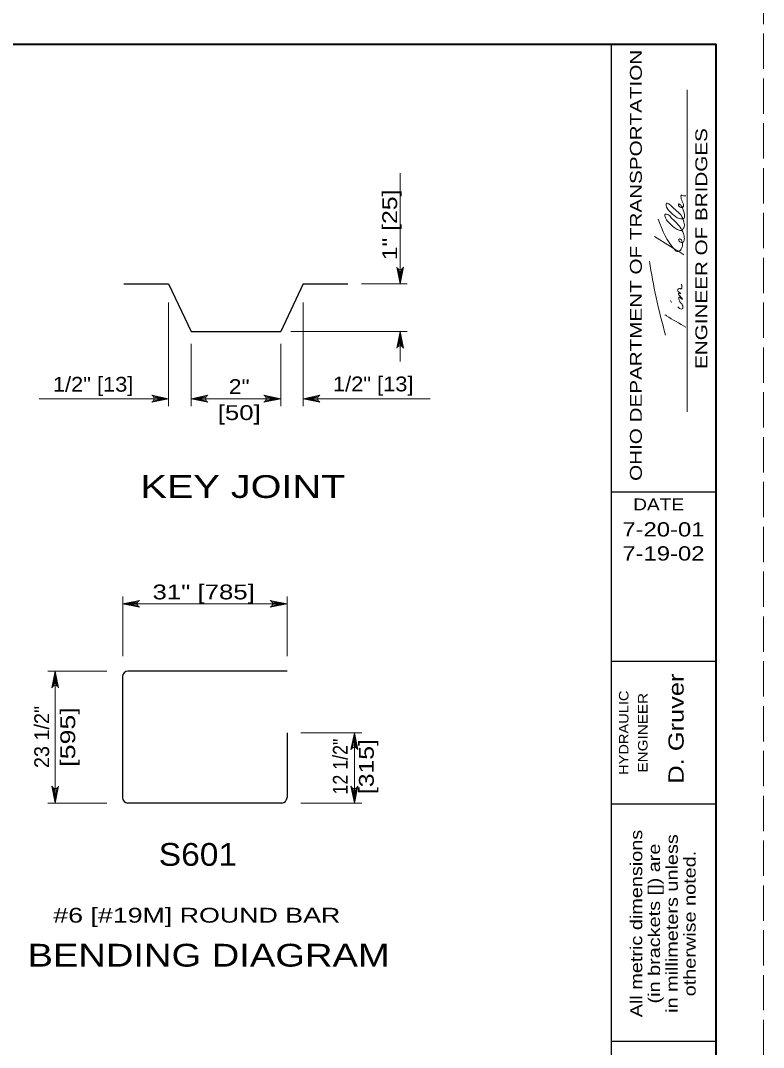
# Model space of a CAD drawing. Extents: x 339.1 to 373.1, y 1412.7 to 1456.7.
# Drawn here: x 365.24 to 373.06, y 1423.68 to 1434.5 of the extents above; entities that cross this region are included whole.
import ezdxf
from ezdxf.enums import TextEntityAlignment as Align

# ---------------------------------------------------------------- set-up
doc = ezdxf.new("R2010")
doc.units = 0
doc.header["$LTSCALE"] = 0.062
doc.linetypes.add('LONG_DASHED', pattern=[7.5, 6, -1.5])
doc.layers.add('1', color=7, linetype='Continuous', lineweight=13)

msp = doc.modelspace()

# ---------------------------------------------------------------- linework, layer by layer
at = {"layer": '1', "lineweight": 25}
for p, q in [((341.0605, 1434.2455), (372.5605, 1434.2455)), ((371.4605, 1413.2455), (371.4605, 1434.2455)), ((372.5605, 1434.2455), (372.5605, 1413.2455)), ((366.32783, 1431.7215), (366.79983, 1431.7215)), ((366.79983, 1431.7215), (367.03583, 1431.22175)), ((368.21583, 1431.7215), (367.97983, 1431.22175)), ((368.21583, 1431.7215), (368.68783, 1431.7215)), ((367.03583, 1431.22175), (367.97983, 1431.22175)), ((372.5605, 1429.52967), (371.4605, 1429.52967)), ((372.5605, 1427.7455), (371.4605, 1427.7455)), ((368.04658, 1427.64575), (366.371, 1427.64575)), ((366.31517, 1427.58658), (366.31517, 1426.31525)), ((368.04658, 1426.99525), (368.04658, 1426.31525)), ((367.99075, 1426.25608), (366.371, 1426.25608)), ((372.5605, 1426.2455), (371.4605, 1426.2455)), ((372.5605, 1423.7455), (371.4605, 1423.7455))]:
    msp.add_line(p, q, dxfattribs=at)
at = {"layer": '1'}
for p, q in [((372.25925, 1430.3765), (372.25925, 1433.76658)), ((369.23558, 1431.7215), (369.23558, 1432.89008)), ((369.21317, 1431.88175), (369.23558, 1431.7215)), ((369.22425, 1431.87625), (369.23558, 1431.7215)), ((369.26033, 1431.88358), (369.23558, 1431.7215)), ((369.25, 1431.8775), (369.23558, 1431.7215)), ((369.23558, 1431.87467), (369.23558, 1431.7215)), ((368.82925, 1431.72217), (369.31142, 1431.72217)), ((372.09175, 1431.52742), (372.08158, 1431.54667)), ((366.79983, 1431.52517), (366.79983, 1430.43508)), ((368.21583, 1431.52517), (368.21583, 1430.43508)), ((368.08683, 1431.22175), (369.31142, 1431.22175)), ((369.21083, 1431.05967), (369.23558, 1431.22175)), ((369.22117, 1431.06575), (369.23558, 1431.22175)), ((369.23558, 1430.90458), (369.23558, 1431.22175)), ((369.23558, 1431.06858), (369.23558, 1431.22175)), ((369.24692, 1431.06692), (369.23558, 1431.22175)), ((369.258, 1431.0615), (369.23558, 1431.22175)), ((367.03583, 1431.09075), (367.03583, 1430.43508)), ((367.97983, 1431.09075), (367.97983, 1430.43508)), ((365.43842, 1430.51375), (366.79983, 1430.51375)), ((366.63775, 1430.489), (366.79983, 1430.51375)), ((366.63958, 1430.53617), (366.79983, 1430.51375)), ((366.64383, 1430.49933), (366.79983, 1430.51375)), ((366.64508, 1430.52508), (366.79983, 1430.51375)), ((366.64667, 1430.51375), (366.79983, 1430.51375)), ((367.19608, 1430.53617), (367.03583, 1430.51375)), ((367.19067, 1430.52508), (367.03583, 1430.51375)), ((367.03583, 1430.51375), (367.72292, 1430.51375)), ((367.189, 1430.51375), (367.03583, 1430.51375)), ((367.19183, 1430.49933), (367.03583, 1430.51375)), ((367.198, 1430.489), (367.03583, 1430.51375)), ((367.69217, 1430.51375), (367.97983, 1430.51375)), ((367.81775, 1430.489), (367.97983, 1430.51375)), ((367.81958, 1430.53617), (367.97983, 1430.51375)), ((367.82383, 1430.49933), (367.97983, 1430.51375)), ((367.82508, 1430.52508), (367.97983, 1430.51375)), ((367.82667, 1430.51375), (367.97983, 1430.51375)), ((368.37608, 1430.53617), (368.21583, 1430.51375)), ((368.37067, 1430.52508), (368.21583, 1430.51375)), ((368.21583, 1430.51375), (369.55125, 1430.51375)), ((368.369, 1430.51375), (368.21583, 1430.51375)), ((368.37183, 1430.49933), (368.21583, 1430.51375)), ((368.378, 1430.489), (368.21583, 1430.51375)), ((366.3195, 1427.80167), (366.3195, 1428.43242)), ((368.04733, 1427.80167), (368.04733, 1428.43242)), ((366.47542, 1428.37617), (366.31517, 1428.35375)), ((366.47, 1428.36508), (366.31517, 1428.35375)), ((366.50417, 1428.35375), (366.31517, 1428.35375)), ((366.46833, 1428.35375), (366.31517, 1428.35375)), ((366.47117, 1428.33933), (366.31517, 1428.35375)), ((366.47733, 1428.32892), (366.31517, 1428.35375)), ((367.36392, 1428.35375), (366.48283, 1428.35375)), ((368.04658, 1428.35375), (367.34017, 1428.35375)), ((367.8845, 1428.32892), (368.04658, 1428.35375)), ((367.88633, 1428.37617), (368.04658, 1428.35375)), ((367.89058, 1428.33933), (368.04658, 1428.35375)), ((367.89183, 1428.36508), (368.04658, 1428.35375)), ((367.89342, 1428.35375), (368.04658, 1428.35375)), ((366.14875, 1427.64575), (365.5285, 1427.64575)), ((365.58242, 1427.48358), (365.60717, 1427.64575)), ((365.59275, 1427.48975), (365.60717, 1427.64575)), ((365.60717, 1427.64575), (365.60717, 1426.732)), ((365.60717, 1427.49258), (365.60717, 1427.64575)), ((365.6185, 1427.49092), (365.60717, 1427.64575)), ((365.62958, 1427.4855), (365.60717, 1427.64575)), ((368.19167, 1426.99683), (368.83325, 1426.99683)), ((368.72983, 1426.83308), (368.75458, 1426.99525)), ((368.74025, 1426.83925), (368.75458, 1426.99525)), ((368.75458, 1426.84208), (368.75458, 1426.99525)), ((368.76592, 1426.84042), (368.75458, 1426.99525)), ((368.777, 1426.835), (368.75458, 1426.99525)), ((368.75458, 1426.99525), (368.75458, 1426.31525)), ((365.60717, 1426.76592), (365.60717, 1426.25617)), ((368.75458, 1426.46167), (368.75458, 1426.25608)), ((365.58475, 1426.41633), (365.60717, 1426.25617)), ((365.59583, 1426.41092), (365.60717, 1426.25617)), ((365.63192, 1426.41825), (365.60717, 1426.25617)), ((365.62158, 1426.41217), (365.60717, 1426.25617)), ((365.60717, 1426.40933), (365.60717, 1426.25617)), ((368.73217, 1426.41633), (368.75458, 1426.25608)), ((368.74325, 1426.41092), (368.75458, 1426.25608)), ((368.77942, 1426.41825), (368.75458, 1426.25608)), ((368.769, 1426.41208), (368.75458, 1426.25608)), ((368.75458, 1426.40925), (368.75458, 1426.25608)), ((366.14875, 1426.25517), (365.5285, 1426.25517)), ((368.19167, 1426.25517), (368.83325, 1426.25517))]:
    msp.add_line(p, q, dxfattribs=at)
at = {"layer": '1', "linetype": 'LONG_DASHED'}
msp.add_lwpolyline([(339.0605, 1412.7455), (373.0605, 1412.7455), (373.0605, 1434.7455), (339.0605, 1434.7455)], close=True, dxfattribs=at)
at = {"layer": '1', "lineweight": 40}
msp.add_lwpolyline([(341.0605, 1434.2455), (372.5605, 1434.2455), (372.5605, 1413.2455), (341.0605, 1413.2455)], close=True, dxfattribs=at)
at = {"layer": '1'}
for points in [[(369.271, 1431.8985), (369.23558, 1431.7215), (369.20017, 1431.8985)], [(369.20017, 1431.04475), (369.23558, 1431.22175), (369.271, 1431.04475)], [(366.62283, 1430.47833), (366.79983, 1430.51375), (366.62283, 1430.54917)], [(367.21283, 1430.47833), (367.03583, 1430.51375), (367.21283, 1430.54917)], [(367.80283, 1430.47833), (367.97983, 1430.51375), (367.80283, 1430.54917)], [(368.39283, 1430.47833), (368.21583, 1430.51375), (368.39283, 1430.54917)], [(366.49217, 1428.31833), (366.31517, 1428.35375), (366.49217, 1428.38908)], [(367.86958, 1428.31833), (368.04658, 1428.35375), (367.86958, 1428.38908)], [(365.57175, 1427.46875), (365.60717, 1427.64575), (365.64258, 1427.46875)], [(368.71925, 1426.81825), (368.75458, 1426.99525), (368.79, 1426.81825)], [(365.64258, 1426.43317), (365.60717, 1426.25617), (365.57175, 1426.43317)], [(368.79, 1426.43308), (368.75458, 1426.25608), (368.71925, 1426.43308)]]:
    msp.add_lwpolyline(points, dxfattribs=at)
for centre, start, end in [((369.23554, 1431.91277), 202.08782, 337.91395), ((369.23562, 1431.03047), 22.08782, 157.91395), ((366.60856, 1430.5138), 292.08605, 67.91218), ((367.22715, 1430.5138), 112.08782, 247.91395), ((367.78856, 1430.5138), 292.08605, 67.91218), ((368.40715, 1430.5138), 112.08782, 247.91395), ((366.50646, 1428.35375), 112.08782, 247.91395), ((367.85532, 1428.35375), 292.08605, 67.91218), ((365.6072, 1427.45445), 22.08782, 157.91395), ((368.75465, 1426.80396), 22.08782, 157.91395), ((365.60712, 1426.44743), 202.08782, 337.91395), ((368.75458, 1426.44739), 202.08782, 337.91395)]:
    msp.add_arc(centre, 0.0382, start, end, dxfattribs=at)
at = {"layer": '1', "lineweight": 25}
for centre, start_param, end_param in [((366.37101, 1427.58658), 6.28318526, 7.85398154), ((366.37101, 1426.31523), 1.57079628, 3.14159256), ((367.99076, 1426.31523), 3.14159275, 4.71238903)]:
    msp.add_ellipse(centre, major_axis=(0, 0.05913), ratio=0.944544, start_param=start_param, end_param=end_param, dxfattribs=at)
at = {"layer": '1'}
for points in [[(371.95233, 1432.4025), (372.1355, 1432.07417), (372.15067, 1432.06358), (372.16083, 1432.06358), (372.19275, 1432.08725), (372.20783, 1432.12142), (372.20283, 1432.17267), (372.18592, 1432.1945), (372.17242, 1432.1945), (372.17067, 1432.1815), (372.18083, 1432.16633), (372.19433, 1432.15792), (372.20942, 1432.15792), (372.22458, 1432.1795), (372.228, 1432.19883), (372.21775, 1432.25417), (372.1355, 1432.37458), (372.09, 1432.41925), (372.05308, 1432.45383), (372.02792, 1432.456), (372.02967, 1432.41742), (372.05483, 1432.37867), (372.12208, 1432.31633), (372.16417, 1432.29092), (372.19783, 1432.28642), (372.22117, 1432.31242), (372.228, 1432.34658), (372.22292, 1432.37233), (372.19275, 1432.4455), (372.1625, 1432.4775), (372.10192, 1432.53092), (372.07325, 1432.55675), (372.03975, 1432.572), (372.03633, 1432.544), (372.04642, 1432.51817), (372.10358, 1432.45825), (372.17425, 1432.411), (372.22625, 1432.41333), (372.22458, 1432.471), (372.21275, 1432.51392), (372.19942, 1432.53967), (372.18925, 1432.55042), (372.16583, 1432.56542), (372.16758, 1432.54833), (372.20283, 1432.52683), (372.21775, 1432.53758), (372.20467, 1432.59125), (372.19608, 1432.61917), (372.19275, 1432.63183), (372.19275, 1432.64467), (372.19275, 1432.65333), (372.21775, 1432.65117), (372.24317, 1432.65117)], [(371.9135, 1432.22025), (372.13725, 1432.08275), (372.22292, 1432.02708)], [(372.02975, 1431.18325), (371.93108, 1431.5785), (371.85983, 1431.96083)], [(372.16083, 1431.48217), (372.16908, 1431.4715), (372.20625, 1431.45858), (372.211, 1431.491), (372.18592, 1431.52742), (372.17067, 1431.56367), (372.17067, 1431.58292), (372.18592, 1431.57667), (372.19608, 1431.56583), (372.20625, 1431.5615), (372.18258, 1431.59367), (372.17067, 1431.60867), (372.16758, 1431.626), (372.191, 1431.61942), (372.18258, 1431.62808), (372.15742, 1431.65592), (372.16758, 1431.67108), (372.18433, 1431.67308), (372.19275, 1431.67108), (372.20283, 1431.69242), (372.19608, 1431.72033)], [(372.24492, 1431.26767), (372.03975, 1431.38767), (372.02417, 1431.39808)]]:
    msp.add_spline(points, degree=3, dxfattribs=at)

# ---------------------------------------------------------------- texts
for s, height, width, p in [('OHIO DEPARTMENT OF TRANSPORTATION', 0.125, 1.3, (371.78042, 1431.91775)), ('ENGINEER OF BRIDGES', 0.125, 1.3, (372.46875, 1432.09454)), ('D. Gruver', 0.16, 1.25, (372.22067, 1427.04)), ('HYDRAULIC', 0.1, 1.15, (371.63958, 1426.99658)), ('ENGINEER', 0.1, 1.2, (371.8405, 1426.99662)), ('[595]', 0.156, 1.35, (365.81625, 1426.95146)), ('12 1/2"', 0.156, 0.9, (368.68508, 1426.63992)), ('[315]', 0.156, 1.25, (368.95908, 1426.63979)), ('All metric dimensions', 0.125, 1.25, (371.78433, 1424.98758)), ('in millimeters unless', 0.125, 1.25, (372.15933, 1424.98762)), ('(in brackets []) are', 0.125, 1.25, (371.97183, 1424.98758)), ('otherwise noted.', 0.125, 1.25, (372.34683, 1424.98758))]:
    msp.add_text(s, height=height, rotation=90, dxfattribs=dict(at, width=width)).set_placement(p, align=Align.CENTER)
at = {"layer": '1', "width": 1.25}
msp.add_text('1" [25]', height=0.156, rotation=90, dxfattribs=at).set_placement((369.20483, 1431.97092))
at = {"layer": '1'}
for s, height, width, p in [('1/2" [13]', 0.156, 1.1, (366.00533, 1430.58767)), ('2"', 0.156, 1.15, (367.54308, 1430.563)), ('[50]', 0.156, 1.3, (367.54317, 1430.289)), ('DATE', 0.125, 1.2, (371.95721, 1429.33825)), ('7-20-01', 0.15, 1.25, (372.00754, 1429.06275)), ('7-19-02', 0.15, 1.25, (372.00754, 1428.80967)), ('31" [785]', 0.156, 1.3, (367.16871, 1428.40075)), ('S601', 0.24, 1.1, (367.10825, 1425.59517))]:
    msp.add_text(s, height=height, dxfattribs=dict(at, width=width)).set_placement(p, align=Align.CENTER)
for s, height, width, p in [('1/2" [13]', 0.156, 1.1, (368.52975, 1430.59108)), ('KEY JOINT', 0.24, 1.3, (366.50367, 1429.46858)), ('#6 [#19M] ROUND BAR', 0.156, 1.35, (365.58617, 1424.99683)), ('BENDING DIAGRAM', 0.24, 1.25, (365.31483, 1424.53392))]:
    msp.add_text(s, height=height, dxfattribs=dict(at, width=width)).set_placement(p)
msp.add_text('23 1/2"', height=0.156, rotation=90, dxfattribs=at).set_placement((365.54225, 1426.9515), align=Align.CENTER)

doc.saveas('drawing.dxf')
